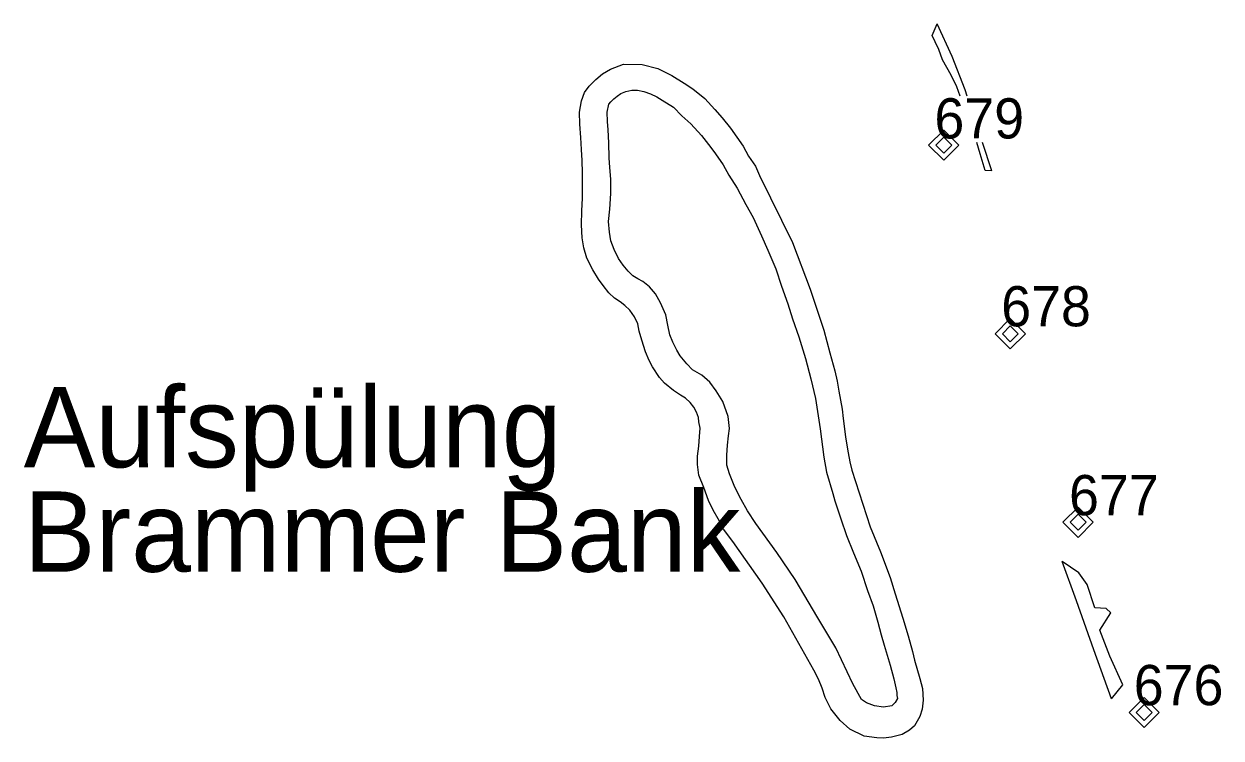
# Model space of a CAD drawing. Extents: x 3461750 to 3585707, y 5917729 to 5985917.
# Drawn here: x 3519729 to 3525687, y 5962175 to 5965729 of the extents above; entities that cross this region are included whole.
import ezdxf

# ---------------------------------------------------------------- set-up
doc = ezdxf.new("R2010")
doc.units = 0
doc.header["$LTSCALE"] = 80
for name, color, linetype, lineweight in [('10', 7, 'Continuous', 13), ('15', 7, 'Continuous', 13), ('2', 7, 'Continuous', 13), ('9', 7, 'Continuous', 13)]:
    doc.layers.add(name, color=color, linetype=linetype, lineweight=lineweight)
doc.layers.add('11', color=7, linetype='Continuous')

msp = doc.modelspace()

# ---------------------------------------------------------------- linework, layer by layer
at = {"layer": '10'}
for points in [[(3524077.2, 5962372.07), (3524064.94, 5962352.05), (3524048.78, 5962336.13), (3524007.42, 5962329.59), (3523962.45, 5962335.94), (3523921.83, 5962350), (3523897.8, 5962367.77), (3523854.83, 5962445.21), (3523770.56, 5962623.63), (3523679.54, 5962772.85), (3523567.87, 5962964.16), (3523476.07, 5963097.85), (3523371.73, 5963243.36), (3523329.88, 5963306.25), (3523298.63, 5963362.11), (3523267.33, 5963424.02), (3523240.23, 5963490.82), (3523227.49, 5963533.79), (3523227.39, 5963582.81), (3523229.88, 5963632.91), (3523236.33, 5963679.88), (3523239.75, 5963716.11), (3523234.13, 5963775.29), (3523206.74, 5963850.29), (3523174.8, 5963903.03), (3523142.09, 5963946.58), (3523102.73, 5963981.54), (3523056.01, 5964007.23), (3523028.42, 5964036.91), (3522995.51, 5964076.76), (3522978.81, 5964105.66), (3522958.84, 5964145.51), (3522944.24, 5964181.25), (3522934.18, 5964229.1), (3522923.93, 5964281.93), (3522897.9, 5964341.7), (3522872.61, 5964385.25), (3522842.92, 5964420.7), (3522809.33, 5964446.97), (3522783.84, 5964460.94), (3522759.77, 5964476.17), (3522735.64, 5964498.73), (3522711.96, 5964527.73), (3522688.53, 5964562.01), (3522666.46, 5964606.05), (3522650.15, 5964648.93), (3522644.04, 5964693.26), (3522638.82, 5964746.09), (3522644.29, 5964807.81), (3522650.59, 5964885.55), (3522650, 5964957.23), (3522645.21, 5965013.77), (3522641.16, 5965063.48), (3522640.09, 5965137.99), (3522636.04, 5965202.34), (3522634.08, 5965242.97), (3522632.13, 5965290.14), (3522640.38, 5965329.59), (3522649.85, 5965341.02), (3522665.14, 5965356.54), (3522682.03, 5965370.02), (3522700.29, 5965382.81), (3522724.61, 5965393.26), (3522755.22, 5965399.02), (3522783.25, 5965398.73), (3522814.55, 5965392.19), (3522846.83, 5965380.37), (3522879.74, 5965366.89), (3522905.96, 5965348.93), (3522961.67, 5965314.94), (3523004.15, 5965271.97), (3523047.56, 5965231.93), (3523101.61, 5965174.32), (3523147.8, 5965114.84), (3523171.29, 5965082.03), (3523209.13, 5965027.73), (3523236.52, 5964976.37), (3523278.27, 5964911.82), (3523321.48, 5964830.76), (3523358.11, 5964766.02), (3523399.66, 5964674.41), (3523431.01, 5964602.93), (3523471.83, 5964510.45), (3523499.66, 5964424.61), (3523530.32, 5964335.64), (3523554.2, 5964260.84), (3523585.94, 5964171.58), (3523619.09, 5964064.36), (3523646, 5963962.99), (3523668.02, 5963864.65), (3523692.58, 5963714.55), (3523709.28, 5963573.34), (3523723.44, 5963497.75), (3523754.69, 5963392.09), (3523765.53, 5963354.88), (3523794.68, 5963265.72), (3523822.22, 5963182.81), (3523857.13, 5963096.29), (3523895.95, 5963004.88), (3523927.39, 5962908.89), (3523955.32, 5962832.52)], [(3523955.32, 5962832.52), (3523979.35, 5962752.05), (3523995.95, 5962688.18), (3524010.5, 5962637.21), (3524025.29, 5962588.09), (3524039.79, 5962537.6), (3524058.25, 5962470.12), (3524069.09, 5962424.8), (3524072.56, 5962401.46), (3524073.49, 5962386.33), (3524077.2, 5962372.07)]]:
    msp.add_lwpolyline(points, dxfattribs=at)
at = {"layer": '15'}
for points in [[(3524306.72, 5965200.49), (3524231.63, 5965125.4), (3524306.72, 5965050.31), (3524381.81, 5965125.4)], [(3524306.72, 5965165.1), (3524267.03, 5965125.4), (3524306.72, 5965085.71), (3524346.41, 5965125.4)], [(3524638.17, 5964262.41), (3524563.08, 5964187.32), (3524638.17, 5964112.23), (3524713.26, 5964187.32)], [(3524638.17, 5964227.01), (3524598.47, 5964187.32), (3524638.17, 5964147.62), (3524677.86, 5964187.32)], [(3524975.23, 5963324.03), (3524900.14, 5963248.94), (3524975.23, 5963173.85), (3525050.32, 5963248.94)], [(3524975.23, 5963288.63), (3524935.54, 5963248.94), (3524975.23, 5963209.25), (3525014.92, 5963248.94)], [(3525304.62, 5962377.06), (3525229.53, 5962301.97), (3525304.62, 5962226.88), (3525379.71, 5962301.97)], [(3525304.62, 5962341.66), (3525264.93, 5962301.97), (3525304.62, 5962262.27), (3525344.32, 5962301.97)]]:
    msp.add_lwpolyline(points, close=True, dxfattribs=at)
at = {"layer": '2'}
msp.add_line((3524546.39, 5964998.44), (3524498.91, 5965139.1), dxfattribs=at)
for points in [[(3524388.43, 5965369.1), (3524371.97, 5965415.43), (3524344.29, 5965474.51), (3524300.98, 5965549.8), (3524281.98, 5965601.46), (3524264.6, 5965640.53), (3524248.68, 5965671.48), (3524273.58, 5965729)], [(3524423.68, 5965369.1), (3524413.23, 5965401.27), (3524348, 5965566.41), (3524273.58, 5965729)], [(3524546.39, 5964998.44), (3524512.3, 5964999.12), (3524488.04, 5965081.84), (3524470.69, 5965139.1)], [(3525142.09, 5962370.9), (3525054.2, 5962614.65), (3524966.89, 5962857.42), (3524895.9, 5963054.3)], [(3525142.09, 5962370.9), (3525197.9, 5962439.65), (3525133.74, 5962581.84), (3525083.11, 5962711.82), (3525137.7, 5962798.14), (3525115.09, 5962819.14), (3525059.47, 5962823.93), (3525021.44, 5962939.55), (3524979.93, 5962996.68), (3524895.9, 5963054.3)]]:
    msp.add_lwpolyline(points, dxfattribs=at)
at = {"layer": '9'}
for points in [[(3522506.3, 5964799.32), (3522508.4, 5964861.13), (3522509.08, 5964926.46), (3522508.79, 5964988.09), (3522506.93, 5965048.93), (3522504.79, 5965104.1), (3522500.88, 5965163.38), (3522495.9, 5965229.98), (3522493.9, 5965290.04), (3522503.37, 5965346.29), (3522518.41, 5965387.89), (3522542.58, 5965419.63), (3522575.54, 5965452.44), (3522608.64, 5965480.37), (3522647.51, 5965503.91), (3522713.33, 5965529.1)], [(3522713.33, 5965529.1), (3522805.71, 5965526.95), (3522883.45, 5965507.91), (3522953.96, 5965471.78), (3523014.75, 5965434.38), (3523058.35, 5965405.27), (3523117.68, 5965357.13), (3523168.12, 5965302.83), (3523203.27, 5965261.52), (3523245.02, 5965209.96), (3523277.83, 5965166.02), (3523308.54, 5965120.61), (3523335.4, 5965071.39), (3523369.24, 5965020.41), (3523390.38, 5964974.9), (3523553.66, 5964640.92), (3523641.94, 5964409.77), (3523709.67, 5964205.47), (3523740.67, 5964092.29), (3523765.33, 5964002.83), (3523776.17, 5963951.76), (3523784.62, 5963901.56), (3523792.92, 5963856.64), (3523800.49, 5963811.91), (3523805.96, 5963764.65), (3523818.21, 5963674.22), (3523823.93, 5963632.42), (3523830.57, 5963593.85), (3523839.89, 5963550.59), (3523850.05, 5963508.11), (3523940.82, 5963226.66), (3523991.41, 5963101.86), (3524039.6, 5962973.54), (3524064.31, 5962893.36), (3524103.71, 5962772.27), (3524129.88, 5962683.01), (3524150.59, 5962606.45), (3524161.72, 5962562.79), (3524187.89, 5962470.7), (3524200.88, 5962422.36), (3524204.39, 5962364.36), (3524199.61, 5962318.46), (3524187.65, 5962282.13), (3524161.77, 5962236.23), (3524135.84, 5962215.04), (3524100.63, 5962193.46), (3524047.02, 5962178.91), (3524006.45, 5962175.1), (3523974.56, 5962176.95), (3523910.25, 5962185.06), (3523840.28, 5962219.63), (3523792.14, 5962263.09), (3523744.97, 5962320.8), (3523716.5, 5962377.64), (3523702.59, 5962423.05), (3523683.5, 5962467.58), (3523660.3, 5962512.89), (3523510.4, 5962778.42), (3523403.56, 5962946.39), (3523257.76, 5963152.93), (3523210.21, 5963214.45), (3523183.74, 5963265.43), (3523160.06, 5963309.38), (3523136.57, 5963356.54), (3523113.18, 5963421.48), (3523087.84, 5963483.01), (3523081.1, 5963536.62), (3523080.91, 5963578.03), (3523087.84, 5963628.32), (3523091.8, 5963675.2), (3523094.34, 5963716.5), (3523087.4, 5963749.12), (3523086.33, 5963769.73), (3523076.27, 5963796.78), (3523062.84, 5963822.27), (3523045.26, 5963845.12), (3523020.8, 5963867.38), (3522997.17, 5963882.32), (3522962.21, 5963905.27), (3522917.82, 5963940.62), (3522892.97, 5963969.34), (3522858.06, 5964022.85), (3522840.19, 5964053.42), (3522822.56, 5964097.85), (3522804.54, 5964155.86), (3522791.7, 5964200.78), (3522784.23, 5964236.91), (3522768.36, 5964271.88), (3522744.04, 5964304.88), (3522719.78, 5964327.34), (3522696.83, 5964345.21), (3522668.31, 5964364.55), (3522640.77, 5964390.14), (3522611.52, 5964427.54), (3522588.09, 5964458.89), (3522559.96, 5964505.57), (3522531.15, 5964563.28), (3522514.94, 5964614.06), (3522507.91, 5964664.94), (3522503.27, 5964728.71), (3522506.3, 5964799.32)]]:
    msp.add_lwpolyline(points, dxfattribs=at)

# ---------------------------------------------------------------- texts
at = {"layer": '11'}
for s, p in [('Aufspülung', (3519728.1, 5963522.6)), ('Brammer Bank', (3519728.1, 5963002.6))]:
    msp.add_text(s, height=400, dxfattribs=at).set_placement(p)
at = {"layer": '15'}
for s, p in [('679', (3524260.4, 5965159.1)), ('678', (3524592.9, 5964224.1)), ('677', (3524930.5, 5963284)), ('676', (3525252.5, 5962338.7))]:
    msp.add_text(s, height=200, dxfattribs=at).set_placement(p)

doc.saveas('drawing.dxf')
